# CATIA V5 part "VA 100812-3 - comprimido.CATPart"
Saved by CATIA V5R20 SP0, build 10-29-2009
Part number: VA 100812-3 - comprimido
Revision: ANY
Definition: UNKNOWN
Nomenclature: VA 100812-3 - comprimido
Source: Unknown
Bounding box of the stored display mesh (mm): x -3.1 to 3.1, y -0.003 to 4.7, z -3.1 to 3.1
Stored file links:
  C:\Users\Utente\Desktop\IO LAVORO\3D X SITO CF\CUMSA\3D files VA\VA 100812\VA 100812-3 - comprimido.CATPart
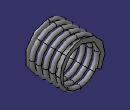
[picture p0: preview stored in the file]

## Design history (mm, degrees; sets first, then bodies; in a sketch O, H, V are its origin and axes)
Body1 "Cortar-Extruir2" (main body)
  Solid1: solid without history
